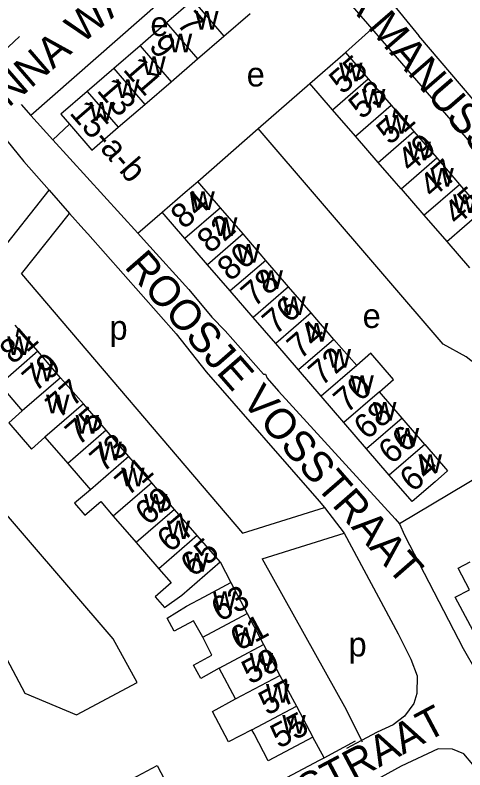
# Model space of a CAD drawing. Extents: x 159902 to 161769, y 383692 to 384875.
# Drawn here: x 160601 to 160675.1, y 383903 to 384027.3 of the extents above; entities that cross this region are included whole.
import ezdxf

# ---------------------------------------------------------------- set-up
doc = ezdxf.new("R2010")
doc.units = 0
for name, color, linetype in [('BLT_Basislijn', 7, 'Continuous'), ('BLT_Bebouwing', 7, 'Continuous'), ('BLT_Centroide', 7, 'Continuous'), ('BLT_Huisnummer', 7, 'Continuous'), ('BLT_Huisnummer_ tussenligend', 7, 'Continuous'), ('BLT_Huisnummer_reeks', 7, 'Continuous'), ('BLT_Onderverdeling_panden', 7, 'Continuous'), ('BLT_Straatnaam', 7, 'Continuous')]:
    doc.layers.add(name, color=color, linetype=linetype)

msp = doc.modelspace()

# ---------------------------------------------------------------- linework, layer by layer
at = {"layer": 'BLT_Basislijn'}
for p, q in [((160658.18, 384035.37), (160667.52, 384023.83)), ((160659.77, 384024.99), (160655.42, 384021.09)), ((160601.76, 384023.74), (160596.48, 384018.79)), ((160678.56, 384010.84), (160667.52, 384023.83)), ((160641.06, 384008.59), (160649.57, 384016.01)), ((160602.03, 384012.54), (160603.61, 384010.75)), ((160603.61, 384010.75), (160607.24, 384006.74)), ((160609.99, 384009.32), (160607.24, 384006.74)), ((160631.1, 383999.89), (160641.06, 384008.59)), ((160671.5, 383973.08), (160641.06, 384008.59)), ((160607.24, 384006.74), (160621.24, 383991.36)), ((160598.17, 383987.78), (160606.62, 383998.44)), ((160606.62, 383998.44), (160609.99, 383994.63)), ((160602.08, 383984.67), (160609.99, 383994.63)), ((160609.99, 383994.63), (160612.33, 383991.97)), ((160621.24, 383991.36), (160625.25, 383994.84)), ((160612.33, 383991.97), (160612.99, 383991.23)), ((160690.47, 383959.11), (160664.32, 383943.52)), ((160651.08, 383947.24), (160651.98, 383946.22)), ((160638.48, 383942.01), (160651.98, 383946.22)), ((160651.98, 383946.22), (160655.24, 383942)), ((160663.62, 383944.35), (160664.32, 383943.52)), ((160641.7, 383937.78), (160655.24, 383942)), ((160634.79, 383937.25), (160636.55, 383933.84)), ((160651.93, 383905.02), (160650.05, 383908.41)), ((160651.93, 383905.02), (160657.08, 383907.83))]:
    msp.add_line(p, q, dxfattribs=at)
for points in [[(160642.26, 384044.96), (160625.02, 384029.48), (160603.61, 384010.75)], [(160645.82, 384040.97), (160648.81, 384037.79), (160649.38, 384036.74), (160651.47, 384034.58), (160659.77, 384024.99)], [(160563.74, 384026.98), (160577.2, 384026.16), (160581.44, 384024.97), (160584.4, 384023.45), (160590.04, 384017.97), (160597.03, 384009.8), (160602.47, 384003.14), (160606.62, 383998.44)], [(160659.77, 384024.99), (160661.45, 384023.04), (160677.02, 384005.07), (160682.46, 383998.27), (160683.74, 383997), (160684.22, 383996.36), (160684.59, 383995.28), (160688.68, 383990.74), (160689.41, 383990.83), (160692.03, 383992.12), (160700, 383997.28)], [(160612.99, 383991.23), (160627.58, 383974.78), (160632.49, 383968.54), (160651.08, 383947.24)], [(160621.24, 383991.36), (160622.69, 383989.77), (160629.66, 383982.09), (160633.42, 383977.54), (160635.65, 383975.31), (160641.96, 383968.14), (160642.28, 383968.14), (160642.54, 383967.5), (160644.38, 383965.35), (160663.62, 383944.35)], [(160602.08, 383984.67), (160638.48, 383942.01)], [(160593.63, 383932.56), (160602.64, 383915.65), (160611.13, 383912.11), (160621.12, 383917.43), (160617.2, 383924.59), (160580.98, 383966.71), (160588.63, 383973.15)], [(160690.47, 383959.11), (160675.33, 383971.02), (160671.5, 383973.08)], [(160664.32, 383943.52), (160665.13, 383941.64), (160674.8, 383922.98), (160676.93, 383919.27)], [(160655.24, 383942), (160664.09, 383925.42), (160666.18, 383921.27), (160667.25, 383918.53), (160667.2, 383915.59), (160666.71, 383913.94), (160665.13, 383911.88), (160663.3, 383910.44), (160660.65, 383909.25), (160658.07, 383907.86)], [(160641.7, 383937.78), (160655.55, 383912.97), (160658.07, 383907.86)], [(160658.07, 383907.86), (160655.6, 383906.53)], [(160658.07, 383907.86), (160658.18, 383907.62)], [(160689.27, 383870.48), (160684.45, 383880.61), (160683.78, 383882.49), (160683.26, 383884.97), (160676.41, 383903.93), (160674.94, 383905.66), (160673.06, 383906.41), (160670.67, 383906.49), (160664.62, 383903.62), (160648.63, 383894.85), (160606.51, 383872.87)], [(160603.18, 383879.15), (160651.15, 383904.6), (160651.93, 383905.02)]]:
    msp.add_lwpolyline(points, dxfattribs=at)
at = {"layer": 'BLT_Bebouwing'}
for p, q in [((160630.29, 384029.71), (160625.95, 384025.96)), ((160635.4, 384023.79), (160639.74, 384027.54)), ((160625.95, 384025.96), (160621.61, 384022.21)), ((160631.06, 384020.04), (160635.4, 384023.79)), ((160621.61, 384022.21), (160617.27, 384018.46)), ((160655.42, 384021.09), (160659.18, 384016.75)), ((160626.71, 384016.29), (160631.06, 384020.04)), ((160617.27, 384018.46), (160612.93, 384014.71)), ((160659.18, 384016.75), (160662.94, 384012.41)), ((160622.37, 384012.54), (160626.71, 384016.29)), ((160653.32, 384011.68), (160649.57, 384016.01)), ((160618.03, 384008.79), (160622.37, 384012.54)), ((160657.08, 384007.34), (160653.32, 384011.68)), ((160662.94, 384012.41), (160666.69, 384008.08)), ((160666.69, 384008.08), (160670.45, 384003.74)), ((160660.83, 384003), (160657.08, 384007.34)), ((160670.45, 384003.74), (160674.21, 383999.4)), ((160634.84, 383995.56), (160631.1, 383999.89)), ((160674.21, 383999.4), (160677.96, 383995.06)), ((160664.59, 383998.67), (160668.35, 383994.33)), ((160638.58, 383991.23), (160634.84, 383995.56)), ((160628.99, 383990.51), (160625.25, 383994.84)), ((160668.35, 383994.33), (160672.1, 383989.99)), ((160632.73, 383986.18), (160628.99, 383990.51)), ((160642.32, 383986.89), (160638.58, 383991.23)), ((160672.1, 383989.99), (160675.86, 383985.66)), ((160646.06, 383982.56), (160642.32, 383986.89)), ((160636.47, 383981.85), (160632.73, 383986.18)), ((160640.21, 383977.51), (160636.47, 383981.85)), ((160649.8, 383978.23), (160646.06, 383982.56)), ((160653.54, 383973.89), (160649.8, 383978.23)), ((160643.95, 383973.18), (160640.21, 383977.51)), ((160604.78, 383971.92), (160601.03, 383976.25)), ((160647.69, 383968.85), (160643.95, 383973.18)), ((160657.28, 383969.56), (160653.54, 383973.89)), ((160608.53, 383967.58), (160604.78, 383971.92)), ((160651.43, 383964.51), (160647.69, 383968.85)), ((160612.28, 383963.25), (160608.53, 383967.58)), ((160598.46, 383966.44), (160602.21, 383962.11)), ((160655.17, 383960.18), (160651.43, 383964.51)), ((160664.76, 383960.9), (160661.02, 383965.23)), ((160616.03, 383958.92), (160612.28, 383963.25)), ((160668.5, 383956.56), (160664.76, 383960.9)), ((160658.91, 383955.85), (160655.17, 383960.18)), ((160619.79, 383954.58), (160616.03, 383958.92)), ((160605.96, 383957.77), (160609.71, 383953.44)), ((160662.65, 383951.52), (160658.91, 383955.85)), ((160623.54, 383950.25), (160619.79, 383954.58)), ((160609.71, 383953.44), (160613.46, 383949.11)), ((160627.29, 383945.91), (160623.54, 383950.25)), ((160631.04, 383941.58), (160627.29, 383945.91)), ((160617.21, 383944.77), (160620.96, 383940.44)), ((160634.79, 383937.25), (160631.04, 383941.58)), ((160620.96, 383940.44), (160624.71, 383936.11)), ((160636.55, 383933.84), (160639.25, 383928.75)), ((160639.25, 383928.75), (160641.95, 383923.67)), ((160641.95, 383923.67), (160644.65, 383918.58)), ((160637.33, 383914.7), (160634.63, 383919.78)), ((160644.65, 383918.58), (160647.35, 383913.49)), ((160647.35, 383913.49), (160650.05, 383908.41))]:
    msp.add_line(p, q, dxfattribs=at)
for points in [[(160649.57, 384016.01), (160651.65, 384017.81), (160655.42, 384021.09)], [(160612.93, 384014.71), (160608.58, 384010.96), (160609.99, 384009.32)], [(160609.99, 384009.32), (160613.69, 384005.04), (160618.03, 384008.79)], [(160664.59, 383998.67), (160663.44, 384000), (160660.83, 384003)], [(160625.25, 383994.84), (160629.04, 383998.11), (160631.1, 383999.89)], [(160661.02, 383965.23), (160663.32, 383967.28), (160659.59, 383971.6), (160657.28, 383969.56)], [(160602.21, 383962.11), (160600.03, 383960.14), (160603.76, 383955.83), (160605.96, 383957.77)], [(160668.5, 383956.56), (160672.24, 383952.23), (160670.18, 383950.45), (160666.39, 383947.18), (160662.65, 383951.52)], [(160613.46, 383949.11), (160610.83, 383946.9), (160612.54, 383944.93), (160615.15, 383947.18), (160617.21, 383944.77)], [(160624.71, 383936.11), (160626.74, 383933.79), (160624.09, 383931.5), (160625.61, 383929.75), (160628.47, 383931.77), (160631.01, 383933.98), (160634.79, 383937.25)], [(160681.61, 383926.68), (160677.27, 383924.37), (160673.51, 383931.44), (160675.85, 383932.68), (160673.96, 383936.22), (160675.96, 383937.29)], [(160631.93, 383924.87), (160630.42, 383927.55), (160627.24, 383925.86), (160626.1, 383928.01), (160629.24, 383929.96), (160632.14, 383931.49), (160636.55, 383933.84)], [(160634.63, 383919.78), (160631.62, 383918.06), (160630.43, 383920.28), (160633.45, 383921.89), (160631.93, 383924.87)], [(160640.03, 383909.61), (160636.19, 383907.62), (160633.53, 383912.66), (160637.33, 383914.7)], [(160650.05, 383908.41), (160642.73, 383904.53), (160640.39, 383908.94), (160640.03, 383909.61)], [(160619.47, 383901.11), (160624.41, 383903.74), (160628.07, 383896.86), (160623.14, 383894.23)]]:
    msp.add_lwpolyline(points, dxfattribs=at)
at = {"layer": 'BLT_Onderverdeling_panden'}
for p, q in [((160630.29, 384029.71), (160635.4, 384023.79)), ((160625.95, 384025.96), (160631.06, 384020.04)), ((160621.61, 384022.21), (160626.71, 384016.29)), ((160617.27, 384018.46), (160622.37, 384012.54)), ((160653.32, 384011.68), (160659.18, 384016.75)), ((160612.93, 384014.71), (160618.03, 384008.79)), ((160657.08, 384007.34), (160662.94, 384012.41)), ((160660.83, 384003), (160666.69, 384008.08)), ((160664.59, 383998.67), (160670.45, 384003.74)), ((160668.35, 383994.33), (160674.21, 383999.4)), ((160634.84, 383995.56), (160628.99, 383990.51)), ((160672.1, 383989.99), (160677.96, 383995.06)), ((160638.58, 383991.23), (160632.73, 383986.18)), ((160642.32, 383986.89), (160636.47, 383981.85)), ((160646.06, 383982.56), (160640.21, 383977.51)), ((160649.8, 383978.23), (160643.95, 383973.18)), ((160653.54, 383973.89), (160647.69, 383968.85)), ((160604.78, 383971.92), (160598.46, 383966.44)), ((160657.28, 383969.56), (160651.43, 383964.51)), ((160608.53, 383967.58), (160602.21, 383962.11)), ((160661.02, 383965.23), (160655.17, 383960.18)), ((160612.28, 383963.25), (160605.96, 383957.77)), ((160664.76, 383960.9), (160658.91, 383955.85)), ((160616.03, 383958.92), (160609.71, 383953.44)), ((160668.5, 383956.56), (160662.65, 383951.52)), ((160619.79, 383954.58), (160613.46, 383949.11)), ((160623.54, 383950.25), (160617.21, 383944.77)), ((160627.29, 383945.91), (160620.96, 383940.44)), ((160631.04, 383941.58), (160624.71, 383936.11)), ((160631.93, 383924.87), (160639.25, 383928.75)), ((160634.63, 383919.78), (160641.95, 383923.67)), ((160637.33, 383914.7), (160644.65, 383918.58)), ((160640.03, 383909.61), (160647.35, 383913.49))]:
    msp.add_line(p, q, dxfattribs=at)

# ---------------------------------------------------------------- texts
at = {"layer": 'BLT_Centroide'}
for s, p in [('w', (160630.67, 384024.88)), ('e', (160623.31, 384023.82)), ('w', (160626.33, 384021.12)), ('w', (160621.98, 384017.38)), ('w', (160654.38, 384016.38)), ('e', (160639.17, 384015.51)), ('w', (160617.66, 384013.62)), ('w', (160658.13, 384012.03)), ('w', (160613.31, 384009.86)), ('w', (160661.88, 384007.72)), ('w', (160665.65, 384003.38)), ('w', (160669.4, 383999.03)), ('w', (160630.05, 383995.19)), ('w', (160673.15, 383994.69)), ('w', (160633.78, 383990.88)), ('w', (160637.52, 383986.53)), ('w', (160641.27, 383982.19)), ('w', (160645.01, 383977.88)), ('e', (160658.26, 383975.76)), ('p', (160616.58, 383973.83)), ('w', (160648.74, 383973.53)), ('w', (160599.74, 383971.34)), ('w', (160652.48, 383969.22)), ('w', (160603.49, 383967)), ('w', (160656.23, 383964.88)), ('w', (160606.13, 383961.72)), ('w', (160659.96, 383960.53)), ('w', (160610.99, 383958.34)), ('w', (160663.7, 383956.22)), ('w', (160614.75, 383954)), ('w', (160667.45, 383951.88)), ('w', (160618.5, 383949.69)), ('w', (160622.25, 383945.34)), ('w', (160626, 383941)), ('w', (160629.03, 383935.66)), ('w', (160633.6, 383929.34)), ('w', (160637.06, 383923.41)), ('p', (160655.94, 383921.7)), ('w', (160639.64, 383919.19)), ('w', (160642.34, 383914.09)), ('w', (160645.03, 383909))]:
    msp.add_text(s, height=4, dxfattribs=at).set_placement(p)
at = {"layer": 'BLT_Huisnummer'}
for s, rotation, p in [('9', 310.8176, (160622.91, 384022.03)), ('55', 40.8874, (160654.92, 384014.07)), ('49', 40.882, (160666.15, 384001.19)), ('45', 40.8887, (160673.79, 383992.48)), ('84', 40.8023, (160628.83, 383991.89)), ('80', 40.8016, (160636.48, 383983.31)), ('76', 40.8064, (160643.9, 383974.48)), ('72', 40.8008, (160651.49, 383966.06)), ('77', 40.8799, (160608.23, 383960.71)), ('68', 40.8056, (160658.96, 383957.21)), ('73', 40.8799, (160615.5, 383951.84)), ('64', 40.8076, (160666.53, 383948.59)), ('69', 40.8799, (160622.96, 383943.09)), ('65', 40.8797, (160630.43, 383934.6)), ('63', 27.9484, (160634.72, 383927.31)), ('59', 27.9487, (160639.73, 383917.01)), ('55', 27.9516, (160644.47, 383906.46))]:
    msp.add_text(s, height=4, rotation=rotation, dxfattribs=at).set_placement(p)
at = {"layer": 'BLT_Huisnummer_ tussenligend'}
for s, rotation, p in [('7', 310.8176, (160627.51, 384025.78)), ('11', 310.8176, (160618.68, 384018.23)), ('13', 310.8176, (160614.36, 384014.78)), ('53', 40.882, (160658.11, 384009.96)), ('51', 40.882, (160662.71, 384005.75)), ('47', 40.8887, (160669.75, 383996.98)), ('82', 40.8016, (160633.16, 383987.89)), ('78', 40.8064, (160640.39, 383979.05)), ('74', 40.8008, (160647.97, 383970.45)), ('81', 40.8799, (160600.68, 383969.63)), ('79', 40.8799, (160604.37, 383965.11)), ('70', 40.8056, (160655.62, 383961.6)), ('75', 40.8799, (160611.46, 383956.24)), ('66', 40.8076, (160663.02, 383953.16)), ('71', 40.8799, (160619.61, 383947.96)), ('67', 40.8797, (160626.56, 383938.64)), ('61', 27.9487, (160637.85, 383922.5)), ('57', 27.9516, (160642.52, 383911.9))]:
    msp.add_text(s, height=4, rotation=rotation, dxfattribs=at).set_placement(p)
at = {"layer": 'BLT_Huisnummer_reeks'}
msp.add_text('15-a-b', height=4, rotation=310.8121, dxfattribs=at).set_placement((160609.86, 384011.09))
at = {"layer": 'BLT_Straatnaam'}
for s, rotation, p in [('ANNA WALRAVENPAD', 40.8188, (160596.57, 384009.03)), ('ROSA MANUSSTRAAT', 310.901, (160645.31, 384040.98)), ('ROOSJE VOSSTRAAT', 311.1071, (160618.89, 383985.78)), ('MARIE JUNGIUSSTRAAT', 28.0378, (160602.91, 383872.48))]:
    msp.add_text(s, height=5, rotation=rotation, dxfattribs=at).set_placement(p)

doc.saveas('drawing.dxf')
